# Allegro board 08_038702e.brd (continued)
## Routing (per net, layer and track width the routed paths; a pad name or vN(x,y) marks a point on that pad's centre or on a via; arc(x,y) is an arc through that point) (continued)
JX_VCCO_13_SEQ: length 4.7
  TOP w0.14: R71.1 R72.2 13.77,38.97 13.51,38.72 11.61,38.72 11.08,39.24 U7.8
JX_VCCO_33_34: length 14.4
  TOP w0.254: R73.1 v1(15.17,39.73)
  TOP w0.305: v1(15.17,39.73) v1(15.67,39.73) 15.86,39.54 Q10.1 ; Q10.1 Q10.2 Q10.5 ; Q10.1 Q10.6
  L14_SIG w0.508: v1(15.67,39.73) v1(15.17,39.73)
  BOTTOM w0.508: JX2.78 61.52,6.56 61.52,6.84 61.9,7.22 61.9,9.04 62.33,9.47 JX2.79 ; JX2.78 61.53,4.05 61.39,3.92 v1(61.39,3.79) ; JX2.78 61.53,6.72 61.77,6.97 62.28,6.97 v1(62.33,6.92) JX2.80
JX_VCCO_33_34_SEQ: length 4
  TOP w0.14: U7.9 11.58,39.38 11.86,39.1 12.63,39.1 12.82,39.29 13.64,39.29 R73.2 R74.1
JX_VIN: length 29.7
  TOP w0.305: Q13.PAD1 16.44,43.36 Q13.5 ; Q13.PAD1 15.79,43.36 Q13.6 ; Q13.PAD1 16.44,42.71 Q13.2 ; Q13.PAD1 15.79,42.71 Q13.1
  TOP w0.406: Q13.1 15.79,41.75 15.17,41.13 v1(15.04,41.13) 14.71,41.13 v1(14.66,41.18)
  L7_SIG w0.406: v1(54.33,4.6) 54.33,6.03 53.9,6.46 53.9,8.92 54.28,9.3 v1(54.28,9.63) 54.28,9.97 v1(54.33,10.01)
  L17_SIG w0.406: v1(53.53,4.56) 54.29,4.56 v1(54.33,4.6)
  BOTTOM w0.203: D1.1 66.04,46.64 65.84,46.84 v1(65.33,46.84)
  BOTTOM w0.254: JX2.59 v1(54.33,10.01)
  BOTTOM w0.508: v1(35.36,4.17) 35.36,5.23 35.13,5.47 JX2.12 ; JX1.59 54.33,56.32 v5(53.77,56.88) 53.53,56.63 JX1.57 ; JX2.60 v1(54.33,4.6) ; v1(53.53,4.56) JX2.58 ; v1(54.33,10.01) 54.24,10.11 54.24,10.23 53.53,10.94 JX2.57 ; JX1.58 53.53,49.76 53.9,49.38 v5(54.03,49.38) 54.15,49.51 54.15,49.64 54.33,49.81 JX1.60
  vias: v1(15.24,43.16) v1(15.32,43.67) v1(16.18,41.76) v3(58.73,21.7) v3(59.23,21.7) v5(53.52,49.38) v5(54.28,56.88)
MGTAVCC: length 10.5
  TOP w0.203: U1.AD6 v1(23.22,38.59) ; U1.AE8 v1(22.22,36.59) ; U1.R4 v1(32.22,40.59) ; U1.AA4 v1(26.22,40.59) ; U1.AC8 v1(24.22,36.59) ; U1.AA8 v1(26.22,36.59) ; U1.Y6 v1(27.22,38.59) ; U1.T6 v1(31.22,38.59) ; U1.U4 v1(30.22,40.59) ; U1.AB6 v1(25.22,38.59)
  TOP w0.305: Q8.4 8.56,37.19 8.94,37.57 v1(9.5,37.57) v1(9.96,37.57)
  BOTTOM w0.305: C222.1 v1(18.21,36.05)
  BOTTOM w0.508: C64.1 26.34,40.46 v1(26.22,40.59) ; C220.1 v1(18.21,38.84)
MGTAVCC_EN: length 16.3
  TOP w0.14: v1(9.58,35.41) 8.82,35.41 8.56,35.67 Q8.3 ; v1(10.21,46.59) 10.08,46.46 U7.25
  L3_SIG w0.095: v1(10.21,46.59) 11.74,45.07 11.74,37.7 10.81,36.77 9.41,36.77 8.94,36.3 8.94,35.67 9.2,35.41 v1(9.58,35.41)
MGTAVTT: length 11.4
  TOP w0.203: U1.T2 v1(31.22,42.59) ; U1.AE4 v1(22.22,40.59) ; U1.AB2 v1(25.22,42.59) ; U1.AD2 v1(23.22,42.59) ; U1.AB7 v1(25.22,37.59) ; U1.Y2 v1(27.22,42.59) ; U1.AF6 v1(21.22,38.59) ; U1.AC4 v1(24.22,40.59) ; U1.V2 v1(29.22,42.59) ; U1.W4 v1(28.22,40.59) ; U1.AF2 v1(21.22,42.59)
  TOP w0.305: Q7.4 10.34,35.16 v1(10.59,34.91) v1(10.97,34.53)
  BOTTOM w0.508: v1(24.22,40.59) 24.31,40.49 C234.1 ; 19.61,37.57 v1(19.61,38.34) ; C223.1 v1(20.37,44.94) ; C221.1 v1(20.37,42.53)
MGTAVTT_EN: length 14.7
  TOP w0.14: Q7.3 10.34,37.15 v1(10.38,37.19) ; U7.26 9.58,46.46 9.1,46.94 9.1,47.13 v1(9.7,47.73)
  L3_SIG w0.095: v1(9.7,47.73) 9.7,47.45 9.36,47.11 9.36,46.83 9.7,46.49 9.7,44.81 11.1,43.42 11.1,42.22 11.38,41.94 11.38,41.6 11.12,41.34 11.12,38.36 10.38,37.62 v1(10.38,37.19)
MGTREFCLK0_112_JX1_N: length 66.9
  L14_SIG w0.089: v1(66.22,53.58) 66.22,54.59 66.47,54.85 71.05,54.85 71.3,55.1 71.3,56.12 71.05,56.37 63.83,56.37 63.43,55.97 63.43,54.57 63.32,54.46 62.51,54.46 62.41,54.57 62.41,55.97 62.01,56.37 60.65,56.37 60.25,55.97 60.25,55.08 60.14,54.97 59.21,54.97 59.11,55.08 59.11,55.97 58.7,56.37 57.6,56.37 56.08,54.85 47.73,54.85 46.49,53.6 46.05,53.6 45.85,53.4 45.44,53.4 45.18,53.14 44.9,53.14 44.89,53.15 43.31,53.15 41.96,51.8 39.8,51.8 39.31,51.3 39.31,48.85 39.2,48.75 37.16,48.75 36.76,48.35 36.76,46.44 36.27,45.96 34.6,45.96 33.82,45.18 33.82,44.08 34.22,43.69 34.22,39.58 33.86,39.22 33.58,39.22 v1(33.22,39.59)
  BOTTOM w0.089: v1(66.22,53.58) 66.05,53.74 66.05,54.34 66.33,54.61 JX1.89 ; C45.1 33.01,39.38 v1(33.22,39.59)
MGTREFCLK0_112_JX1_P: length 66.8
  L14_SIG w0.089: v1(33.22,38.59) 33.58,38.95 33.58,38.97 33.96,38.97 34.47,39.48 34.47,43.8 34.08,44.19 34.08,45.08 34.7,45.7 36.37,45.7 37.01,46.34 37.01,48.24 37.26,48.5 39.31,48.5 39.56,48.75 39.56,51.19 39.91,51.54 42.07,51.54 43.42,52.89 44.79,52.89 44.79,52.89 45.28,52.89 45.55,53.15 45.96,53.15 46.16,53.35 46.6,53.35 47.84,54.59 56.19,54.59 57.71,56.12 58.6,56.12 58.85,55.86 58.85,54.97 59.11,54.72 60.25,54.72 60.5,54.97 60.5,55.86 60.76,56.12 61.9,56.12 62.16,55.86 62.16,54.46 62.41,54.21 63.43,54.21 63.68,54.46 63.68,55.86 63.93,56.12 70.94,56.12 71.05,56.01 71.05,55.2 70.94,55.1 66.53,55.1 66.53,55.1 66.37,55.1 65.97,54.7 65.97,54.59 65.84,54.46 65.84,54.21 65.97,54.08 65.97,53.96 v1(65.58,53.58)
  BOTTOM w0.089: C47.1 33.01,38.38 v1(33.22,38.59) ; v1(65.58,53.58) 65.84,53.83 65.84,54.34 65.53,54.65 JX1.87
MGTREFCLK1_112_JX3_N: length 68.5
  L3_SIG w0.089: v1(13.77,12.17) 13.58,11.98 13.01,11.98 12.77,11.75 12.77,10.91 14.53,9.15 14.53,4.58 14.93,4.17 15.93,4.17 16.18,3.92 16.18,3.56 16.58,3.16 17.83,3.16 18.09,3.41 18.09,10.9 18.3,11.11 18.3,12.06 18.49,12.26 19.95,12.26 20.37,12.68 22.26,12.68 22.66,13.08 22.66,16.62 22.15,17.13 20.75,17.13 20.5,17.38 20.5,35.56 20.73,35.8 20.95,35.8 21.08,35.92 29.46,35.92 29.88,36.34 29.88,38.84 29.49,39.22 28.69,39.22 28.68,39.22 28.59,39.22 v1(28.22,39.59)
  BOTTOM w0.089: v1(28.22,39.59) 28.58,39.22 29.39,39.22 29.61,39 C48.1 ; v1(13.77,12.17) 13.58,11.98 13.45,11.98 13.26,12.17 JX3.4
MGTREFCLK1_112_JX3_P: length 68.4
  L3_SIG w0.089: v1(13.77,11.54) 13.58,11.73 13.11,11.73 13.02,11.64 13.02,11.01 14.78,9.25 14.78,4.68 15.04,4.43 16.03,4.43 16.44,4.02 16.44,3.66 16.69,3.41 17.73,3.41 17.83,3.52 17.83,11.01 18.04,11.22 18.04,12.16 18.39,12.51 19.84,12.51 20.27,12.94 22.15,12.94 22.4,13.19 22.4,16.51 22.04,16.87 20.65,16.87 20.25,17.28 20.25,35.67 20.63,36.05 20.84,36.05 20.97,36.18 29.36,36.18 29.63,36.45 29.63,38.73 29.39,38.97 28.79,38.97 28.78,38.96 28.48,38.96 28.3,39.15 27.92,39.15 27.74,38.97 27.74,38.42 27.83,38.34 27.96,38.34 v1(28.22,38.59)
  BOTTOM w0.089: v1(28.22,38.59) 28.69,38.11 C46.1 ; v1(13.77,11.54) 13.64,11.67 13.51,11.67 13.22,11.37 JX3.2
MGTXRX0_112_JX1_N: length 66.8
  TOP w0.089: U1.AB3 v1(25.22,41.59)
  L6_SIG w0.089: v1(25.22,41.59) 24.88,41.25 22.04,41.25 21.97,41.18 21.63,40.83 21.63,40.34 21.64,40.33 21.64,39.33 21.54,39.22 20.1,39.22 19.99,39.33 19.99,45.6 20.1,45.7 35.72,45.7 36.99,46.97 44.38,46.97 45.39,47.99 52.48,47.99 52.99,48.5 54.81,48.5 55.06,48.24 55.06,47.35 55.32,47.1 56.87,47.1 57.15,46.83 57.64,46.83 57.68,46.86 58.47,46.86 58.71,47.1 59.38,47.1 59.61,46.86 61.16,46.86 61.38,46.89 61.77,46.89 61.89,47.02 62.53,47.02 62.61,47.1 63.22,47.1 63.31,47.02 64.61,47.02 65.19,47.59 65.44,47.59 65.84,47.99 65.84,48.88 65.97,49 66.17,49 66.35,49.18 66.35,49.33 v1(66.03,49.65)
  BOTTOM w0.089: JX1.90 66.33,50.25 65.97,49.89 65.97,49.71 v1(66.03,49.65)
MGTXRX0_112_JX1_P: length 66.8
  TOP w0.089: U1.AB4 v1(25.22,40.59)
  L6_SIG w0.089: v1(65.52,49.64) 65.58,49.57 65.58,48.09 65.34,47.85 65.09,47.85 64.51,47.27 63.41,47.27 63.33,47.35 62.5,47.35 62.42,47.27 61.79,47.27 61.66,47.14 61.19,47.14 61.16,47.12 61.15,47.12 59.72,47.12 59.48,47.35 58.6,47.35 58.37,47.12 57.57,47.12 57.53,47.08 57.25,47.08 56.98,47.35 55.42,47.35 55.32,47.46 55.32,48.35 54.92,48.75 54.71,48.75 52.88,48.75 52.38,48.24 45.26,48.24 44.25,47.23 36.88,47.23 35.61,45.96 19.99,45.96 19.74,45.7 19.74,39.22 19.99,38.97 21.64,38.97 21.9,39.22 21.9,40.43 21.88,40.45 21.88,40.73 22.08,40.92 22.08,40.92 22.15,41 24.81,41 v1(25.22,40.59)
  BOTTOM w0.089: v1(65.52,49.64) 65.75,49.87 65.75,49.89 65.53,50.11 JX1.88
MGTXRX1_112_JX1_N: length 67.9
  TOP w0.089: U1.Y3 v1(27.22,41.59)
  L4_SIG w0.089: v1(67.74,53.58) 67.74,53.91 67.62,54.03 67.62,54.57 66.83,55.35 36.08,55.35 30.54,49.81 30.54,49.75 28.65,47.86 27.76,47.86 27.44,47.54 27.44,47.09 27.36,47 27.36,46.1 27.76,45.7 33.22,45.7 33.83,45.09 33.83,40.6 33.47,40.24 29.09,40.24 28.81,40.52 28.81,40.83 28.46,41.18 27.82,41.18 27.78,41.22 27.59,41.22 v1(27.22,41.59)
  BOTTOM w0.089: JX1.93 67.93,54.69 67.58,54.34 67.58,53.74 v1(67.74,53.58)
MGTXRX1_112_JX1_P: length 68
  TOP w0.089: U1.Y4 v1(27.22,40.59)
  L4_SIG w0.089: v1(27.22,40.59) 27.1,40.7 27.1,41 27.21,41.11 27.34,41.11 27.48,40.96 27.68,40.96 27.71,40.92 28.35,40.92 28.55,40.73 28.55,40.42 28.98,39.99 33.58,39.99 34.09,40.49 34.09,45.19 33.33,45.96 27.87,45.96 27.61,46.21 27.61,46.9 27.69,46.98 27.69,47.44 27.87,47.61 28.75,47.61 30.79,49.64 30.79,49.7 36.19,55.1 66.73,55.1 67.36,54.46 67.36,54.03 67.24,53.91 v1(67.24,53.58)
  BOTTOM w0.089: v1(67.24,53.58) 67.36,53.7 67.36,54.34 67.13,54.57 JX1.91
MGTXRX2_112_JX1_N: length 66.8
  TOP w0.089: U1.V3 v1(29.22,41.59)
  L6_SIG w0.089: v1(67.74,49.69) 67.92,49.51 68.07,49.51 68.2,49.38 68.2,49.21 68,49 67.87,49 67.74,48.88 67.74,46.1 66.95,45.31 64.86,45.31 63.94,46.23 52.29,46.23 52.24,46.29 51.96,46.29 51.9,46.23 49.46,46.23 49.18,45.96 38.38,45.96 36.35,43.92 34.6,43.92 34.34,43.67 34.34,42.25 34.09,42 32.82,42 32.56,42.25 32.56,43.67 32.55,43.68 32.55,43.73 32.35,43.92 32.31,43.92 32.31,43.92 22,43.92 21.9,43.82 21.9,42.28 22,42.18 26.46,42.18 26.88,41.76 26.88,41.45 27.08,41.25 28.88,41.25 v1(29.22,41.59)
  BOTTOM w0.089: JX1.94 67.93,50.33 67.62,50.02 67.62,49.81 v1(67.74,49.69)
MGTXRX2_112_JX1_P: length 66.8
  TOP w0.089: U1.V4 v1(29.22,40.59)
  L6_SIG w0.089: v1(67.24,49.69) 67.49,49.43 67.49,46.21 66.84,45.56 64.97,45.56 64.04,46.49 52.4,46.49 52.34,46.55 51.85,46.55 51.8,46.49 49.35,46.49 49.07,46.21 38.28,46.21 36.25,44.18 34.49,44.18 34.09,43.78 34.09,42.36 33.98,42.25 32.92,42.25 32.82,42.36 32.82,43.78 32.81,43.79 32.81,43.83 32.46,44.18 32.42,44.18 21.9,44.18 21.64,43.92 21.64,42.18 21.9,41.92 26.35,41.92 26.63,41.65 26.63,41.34 26.97,41 28.81,41 v1(29.22,40.59)
  BOTTOM w0.089: JX1.92 67.13,50.29 67.4,50.02 67.4,49.85 v1(67.24,49.69)
MGTXRX3_112_JX1_N: length 66.8
  TOP w0.089: U1.T3 v1(31.22,41.59)
  L4_SIG w0.089: v1(70.16,53.58) 70.16,53.91 69.97,54.1 69.97,54.53 68.12,56.37 35,56.37 28.13,49.5 26.97,49.5 25.45,47.99 25.45,45.47 26.74,44.18 32.2,44.18 32.55,43.83 32.55,41.45 32.35,41.25 31.55,41.25 v1(31.22,41.59)
  BOTTOM w0.089: JX1.99 70.33,54.67 69.99,54.34 69.99,53.74 v1(70.16,53.58)
MGTXRX3_112_JX1_P: length 66.7
  TOP w0.089: U1.T4 v1(31.22,40.59)
  L4_SIG w0.089: v1(31.22,40.59) 31.17,40.64 31.17,41 31.24,41.07 31.37,41.07 31.45,41 32.46,41 32.81,41.34 32.81,43.94 32.31,44.43 26.85,44.43 25.71,45.57 25.71,47.88 27.07,49.25 28.24,49.25 35.1,56.12 68.02,56.12 69.71,54.42 69.71,54.1 69.52,53.91 v1(69.52,53.58)
  BOTTOM w0.089: v1(69.52,53.58) 69.78,53.83 69.78,54.34 69.53,54.59 JX1.97
MGTXTX0_112_JX3_N: length 67.3
  TOP w0.089: U1.AA1 v1(26.22,43.59)
  L3_SIG w0.089: v1(16.82,16.11) 17.08,16.31 17.16,16.31 17.42,16.56 17.42,17.89 17.16,18.14 17.07,18.14 16.82,18.4 16.82,19.41 17.07,19.67 18.06,19.67 18.47,19.26 18.47,14.23 18.06,13.82 13.87,13.82 13.77,13.72 13.77,13.29 13.87,13.19 18.91,13.19 19.02,13.29 19.02,14.44 19.42,14.84 21.54,14.84 21.64,14.95 21.64,15.37 21.54,15.48 19.42,15.48 19.02,15.88 19.02,31.1 18.59,31.52 18.59,33.64 19.02,34.06 19.02,36.35 19.86,37.19 20.88,37.19 21.9,38.21 21.9,39.46 22.91,40.47 22.91,41.64 24.45,43.18 25.46,43.18 25.48,43.16 25.79,43.16 v1(26.22,43.59)
  BOTTOM w0.089: v1(16.82,16.11) 16.82,15.78 16.38,15.35 15.46,15.35 14.4,14.29 13.64,14.29 13.36,14.57 JX3.10
MGTXTX0_112_JX3_P: length 67.3
  TOP w0.089: U1.AA2 v1(26.22,42.59)
  L3_SIG w0.089: v1(17.2,15.6) 17.41,15.76 17.41,16.2 17.67,16.46 17.67,17.99 17.27,18.4 17.18,18.4 17.07,18.5 17.07,19.31 17.18,19.41 17.96,19.41 18.21,19.16 18.21,14.33 17.96,14.08 13.77,14.08 13.51,13.82 13.51,13.19 13.77,12.94 19.02,12.94 19.27,13.19 19.27,14.33 19.53,14.59 21.64,14.59 21.9,14.84 21.9,15.48 21.64,15.73 19.53,15.73 19.27,15.98 19.27,31.2 18.85,31.63 18.85,33.53 19.27,33.96 19.27,36.24 19.97,36.94 20.99,36.94 22.15,38.1 22.15,39.35 23.17,40.37 23.17,41.53 24.56,42.92 25.35,42.92 25.37,42.91 25.9,42.91 v1(26.22,42.59)
  BOTTOM w0.089: v1(17.2,15.6) 16.94,15.6 16.47,15.13 15.55,15.13 14.49,14.08 13.64,14.08 13.33,13.77 JX3.8
MGTXTX1_112_JX3_N: length 67.3
  TOP w0.089: U1.W1 v1(28.22,43.59)
  L18_SIG w0.089: v1(28.22,43.59) 27.84,43.22 22.59,43.22 20.12,40.75 20.12,40.16 18.98,39.01 18.98,35.54 17.45,34.02 12.98,34.02 12.75,34.25 12.75,34.56 12.67,34.64 12.67,34.92 12.75,35 12.75,35.31 13.13,35.69 13.13,38.52 12.69,38.97 12.06,38.97 11.61,38.52 11.61,33.13 12.24,32.49 12.37,32.49 12.75,32.11 12.75,30.21 13.13,29.83 15.42,29.83 15.67,30.08 15.67,32.24 15.93,32.49 16.38,32.49 16.56,32.31 16.56,30.92 17.14,30.33 17.58,30.33 18.09,29.83 18.09,27.79 17.32,27.03 16.69,27.03 15.67,26.02 14.78,26.02 13.01,24.24 13.01,19.54 11.86,18.4 11.13,18.4 10.2,17.47 9.86,17.13 v1(9.7,17.13)
  BOTTOM w0.089: v1(9.7,17.13) 9.7,16.87 9.45,16.62 9.2,16.62 8.84,16.97 JX3.15
MGTXTX1_112_JX3_P: length 67.3
  TOP w0.089: U1.W2 v1(28.22,42.59)
  L18_SIG w0.089: v1(10.21,16.75) 10.21,17.12 11.23,18.14 11.97,18.14 13.26,19.43 13.26,24.13 14.89,25.76 15.78,25.76 16.79,26.78 17.43,26.78 18.34,27.69 18.34,29.93 17.68,30.59 17.25,30.59 16.82,31.02 16.82,32.41 16.48,32.75 15.82,32.75 15.42,32.34 15.42,30.19 15.31,30.08 13.24,30.08 13.01,30.31 13.01,32.22 12.48,32.75 12.35,32.75 11.86,33.23 11.86,38.42 12.16,38.72 12.58,38.72 12.88,38.42 12.88,35.8 12.5,35.41 12.5,35.11 12.42,35.02 12.42,34.53 12.5,34.45 12.5,34.14 12.88,33.76 17.56,33.76 19.23,35.44 19.23,38.91 20.37,40.05 20.37,40.64 22.69,42.96 27.84,42.96 v1(28.22,42.59)
  BOTTOM w0.089: JX3.13 8.97,16.17 9.2,16.4 9.54,16.4 9.88,16.75 v1(10.21,16.75)
MGTXTX2_112_JX3_N: length 67.3
  TOP w0.089: U1.U1 v1(30.22,43.59)
  L3_SIG w0.089: v1(30.22,43.59) 29.84,43.22 29.75,43.22 29.72,43.25 29.14,43.25 29.08,43.25 28.88,43.45 28.88,44.05 28.43,44.51 21.08,44.51 19.61,43.03 19.61,40.37 18.68,39.44 18.68,37.51 17.58,36.41 17.58,35.92 17.32,35.67 11.61,35.67 11.36,35.41 11.36,33.91 11.76,33.51 17.22,33.51 17.32,33.4 17.32,31.2 17.22,31.1 15.67,31.1 15.42,31.35 14.4,31.35 14.15,31.1 11.61,31.1 11.36,30.84 11.36,29.32 11.61,29.06 15.67,29.06 15.93,29.32 17.07,29.32 17.58,28.81 17.58,21.55 14.78,18.76 14.78,16.94 14.59,16.75 14.48,16.75 14.35,16.87 v1(14.02,16.87)
  BOTTOM w0.089: JX3.16 13.38,16.97 13.64,16.71 13.86,16.71 v1(14.02,16.87)
MGTXTX2_112_JX3_P: length 67.3
  TOP w0.089: U1.U2 v1(30.22,42.59)
  L3_SIG w0.089: v1(30.22,42.59) 29.84,42.96 29.65,42.96 29.61,43 29.03,43 28.97,43 28.63,43.34 28.63,43.95 28.32,44.25 21.19,44.25 19.86,42.93 19.86,40.26 18.94,39.33 18.94,37.41 17.83,36.3 17.83,35.82 17.43,35.41 11.71,35.41 11.61,35.31 11.61,34.02 11.86,33.76 17.32,33.76 17.58,33.51 17.58,31.1 17.32,30.84 15.57,30.84 15.31,31.1 14.51,31.1 14.25,30.84 11.71,30.84 11.61,30.74 11.61,29.42 11.71,29.32 15.57,29.32 15.82,29.57 17.18,29.57 17.83,28.92 17.83,21.44 15.04,18.65 15.04,16.83 14.7,16.49 14.48,16.49 14.35,16.36 v1(14.02,16.36)
  BOTTOM w0.089: JX3.14 13.32,16.17 13.64,16.49 13.9,16.49 v1(14.02,16.36)
MGTXTX3_112_JX3_N: length 67.7
  TOP w0.089: U1.R1 v1(32.22,43.59)
  L18_SIG w0.089: v1(32.22,43.59) 31.86,43.24 30.09,43.24 29.88,43.45 29.88,43.76 29.33,44.3 20.5,44.3 19.78,43.59 19.78,41.55 19.23,41 19.23,40.47 18.19,39.43 17.97,39.43 17.63,39.1 16.05,39.1 15.91,39.24 14.28,39.24 13.9,39.62 13.9,40.02 13.69,40.23 13.69,41.78 13.9,41.99 13.9,42.53 13.51,42.91 11.61,42.91 11.38,42.68 11.38,41.61 11.23,41.45 11.23,40.37 10.85,39.99 8.82,39.99 8.43,39.61 8.43,33.76 11.74,30.46 11.74,28.81 12.12,28.43 14.28,28.43 14.78,28.94 15.9,28.94 16.09,28.75 16.09,28.48 16.35,28.23 16.35,27.95 16.16,27.75 15.72,27.75 15.01,27.03 14.53,27.03 11.74,24.24 11.74,19.79 11.31,19.37 11.31,19.29 11.05,19.03 10.29,19.03 10.16,19.16 v1(9.83,19.16)
  BOTTOM w0.089: v1(9.83,19.16) 9.7,19.03 9.2,19.03 8.86,19.37 JX3.21
MGTXTX3_112_JX3_P: length 67.7
  TOP w0.089: U1.R2 v1(32.22,42.59)
  L18_SIG w0.089: v1(32.22,42.59) 31.82,42.98 29.99,42.98 29.63,43.34 29.63,43.65 29.23,44.05 20.6,44.05 20.04,43.48 20.04,41.45 19.48,40.9 19.48,40.37 18.3,39.18 18.07,39.18 17.74,38.84 15.95,38.84 15.8,38.99 14.17,38.99 13.64,39.52 13.64,39.91 13.43,40.12 13.43,41.88 13.64,42.09 13.64,42.42 13.41,42.65 11.71,42.65 11.64,42.57 11.64,41.5 11.48,41.35 11.48,40.26 10.95,39.73 8.92,39.73 8.69,39.5 8.69,33.87 11.99,30.57 11.99,28.92 12.22,28.68 14.17,28.68 14.68,29.19 16.01,29.19 16.35,28.85 16.35,28.59 16.61,28.33 16.61,27.84 16.26,27.5 15.83,27.5 15.11,26.78 14.64,26.78 11.99,24.13 11.99,19.69 11.56,19.26 11.56,19.19 11.15,18.78 10.29,18.78 10.16,18.65 v1(9.83,18.65)
  BOTTOM w0.089: JX3.19 8.95,18.57 9.2,18.82 9.67,18.82 v1(9.83,18.65)
Net_65: length 0.6
  TOP w0.14: v6(70,30.49) 69.6,30.09
PG_1P8V: length 16.7
  TOP w0.305: v1(70.41,5.06) 69.86,5.61 U19.4 ; v1(67.24,4.43) 66.73,4.93 66.73,5.35 66.68,5.4 66.66,5.42 66.24,5.84 64.17,5.84 63.81,6.2 R81.1 63.3,6.84 62.79,7.35 62.54,7.35 62.26,7.62 U4.1
  TOP w0.381: U20.4 79.51,6.37 v1(79.81,6.08)
  L3_SIG w0.406: v1(34.47,4.93) 34.47,3.86 35.17,3.16 36.37,3.16 37.26,2.27 v1(37.64,2.27)
  BOTTOM w0.508: JX2.10 34.33,5.08 v1(34.47,4.93)
PG_MODULE: length 90.9
  TOP w0.14: Q14.1 v1(30.51,50.68) ; R43.2 30.66,11.79 v1(30.41,12.05) ; v1(14.49,46.59) 14.49,46.54 14.22,46.27 14.22,46.27 14.09,46.15 13.74,46.15 13.42,46.46 12.37,46.46 12.08,46.17 U7.21
  L3_SIG w0.095: v1(30.41,12.05) 30.91,12.05 31.93,13.06 v3(34.22,13.06)
  L14_SIG w0.095: v1(30.51,50.68) 30.48,50.65 29.26,50.65 27.23,48.62 20.25,48.62 19.36,47.73 16.31,47.73 15.17,46.59 v1(14.49,46.59)
  L18_SIG w0.095: v1(30.51,50.68) 30.53,50.65 30.53,47.86 31.42,46.97 32.35,46.97 32.61,46.72 32.61,44.8 32.8,44.6 33.41,44.6 34.72,43.29 34.72,36.43 35.23,35.93 35.36,35.93 35.56,35.73 35.56,34.04 35.78,33.82 35.78,33.15 36,32.93 36.36,32.93 36.54,32.75 36.64,32.75 36.88,32.51 36.88,32.45 37.07,32.25 37.14,32.25 37.27,32.11 37.37,32.11 37.75,31.73 37.75,31.35 39.18,29.93 39.36,29.93 39.56,29.73 39.56,29.55 39.88,29.23 39.88,28.63 39.55,28.31 39.45,28.31 38.88,27.73 38.88,27.11 38.7,26.93 38.07,26.93 37.88,26.73 37.55,26.73 37.36,26.93 35.07,26.93 34.93,26.78 33.51,26.78 33.36,26.93 33.07,26.93 32.88,26.73 32.88,26.11 32.7,25.93 32.06,25.93 31.16,25.03 30.17,25.03 29.78,24.64 29.78,24.36 29.45,24.03 29.17,24.03 28.88,23.73 28.88,23.45 28.39,22.97 27.12,22.97 26.82,22.67 26.82,20.27 26.93,20.15 27.45,20.15 27.83,19.76 27.83,18.44 28.12,18.15 28.45,18.15 28.78,17.82 28.78,17.49 29.44,16.83 29.66,16.83 30.63,15.86 32.95,15.86 34.6,14.21 34.6,13.44 v3(34.22,13.06)
  L19_GND w0.203: v3(34.22,13.06) 34.34,13.06 v4(35.13,12.28)
  BOTTOM w0.14: v4(35.13,12.28) JX2.11
PHY1_1V8: length 12.8
  TOP w0.406: E14.2 v1(30.91,2.01)
  TOP w0.508: C78.1 16.35,17.67 v1(16.18,17.51)
  BOTTOM w0.305: U10.10 v1(20.39,2.39) 20.12,2.39 19.89,2.62 U10.11 ; v1(27.1,8.74) v1(27.1,8.24) 27.1,7.86 26.59,7.34 U10.49 25.59,7.35 24.94,7.35 24.69,7.09 24.69,6.08 24.92,5.84 U10.52
  BOTTOM w0.406: v1(30.91,2.01) 31.17,2.27 v1(31.17,2.78) ; v1(29.77,4.43) 29.14,3.79 R11.1
  BOTTOM w0.508: v1(15.42,3.79) 15.55,3.79 15.8,4.05 C74.1 ; C206.1 v1(15.8,6.46)
PHY1_AVDD_1V8: length 117.5
  TOP w0.305: C201.1 C218.1 22.28,12.43 v1(22.89,11.81)
  TOP w0.508: C211.1 v1(19.23,11.79) 18.47,11.03 C203.1
  L3_SIG w0.406: v1(72.44,11.28) v1(73.2,11.28)
  L3_SIG w0.508: v1(22.89,11.81) 23.7,11 24.22,11 24.32,10.9 27.99,10.9 28.5,10.4 35.1,10.4 36.12,9.38 36.12,4.81 37.52,3.41 43.49,3.41 43.87,3.03 50.98,3.03 52.25,1.76 63.04,1.76 65.08,3.79 65.08,5.82 67.36,8.11 67.36,10.14 68,10.78 69.78,10.78 70.66,11.67 72.06,11.67 v1(72.44,11.28)
  L19_GND w0.305: v4(18.7,5.84) v3(19.21,5.84)
  L19_GND w0.406: v4(23.89,4.17) 23.93,4.17 24.44,4.68 v3(24.44,5.06)
  BOTTOM w0.254: v1(16.18,9.89) 16.4,9.67 16.61,9.67 16.94,9.34 U10.26 ; v4(23.89,4.17) U10.3
  BOTTOM w0.305: U10.39 23.39,10.62 22.91,10.14 22.69,10.14 v1(22.53,9.99) ; U10.38 v1(22.89,11.81) ; U10.35 21.39,11.66 v1(21.26,11.79) ; v1(74.47,42.15) 74.74,42.15 75.13,42.53 U24.5 ; U10.19 v4(18.7,5.84)
  BOTTOM w0.406: C210.1 22.15,13.57 21.26,12.68 v1(21.26,11.79) ; v1(72.44,11.28) v1(73.2,11.28) 74.22,12.3 74.22,16.49 77.14,19.41 77.14,37.07 75.62,38.59 74.6,38.59 73.59,39.61 73.59,41.26 v1(74.47,42.15)
  BOTTOM w0.508: v1(14.02,8.74) 14.44,9.16 C219.1
PHY1_AVDD_3V3: length 8.7
  TOP w0.406: C208.1 15.8,9.25 v1(16.44,9.25) ; C49.1 v1(17.71,11.92)
  TOP w0.508: C217.1 v1(24.82,12.55) ; E15.2 v1(15.55,18.02)
  L19_GND w0.305: v3(19.23,6.59) 18.99,6.34 v4(18.46,6.34)
  BOTTOM w0.203: 16.96,6.34 U10.20
  BOTTOM w0.254: v1(16.44,9.25) 16.78,8.91 16.99,8.91 17.06,8.84 U10.25
  BOTTOM w0.305: U10.20 v4(18.46,6.34)
  BOTTOM w0.508: C214.1 16.93,6.34 16.96,6.34
PHY1_DVDD_1V0: length 22.4
  TOP w0.406: C63.1 v1(27.87,12.55)
  TOP w0.457: v1(24.89,11.74) 24.85,11.7 v1(23.89,11.7)
  TOP w0.508: v1(27.87,12.55) 28.08,12.34 C58.1 ; v1(23.89,11.7) 23.8,11.79 C73.1 ; C63.1 v1(26.21,12.55)
  L6_SIG w0.508: v1(22.15,1.51) 22.15,2.01 23.29,3.16 23.8,3.16 24.94,4.3 24.94,4.8 24.98,4.84 24.98,5.29 24.94,5.33 24.94,5.95 25.71,6.71 25.71,9.63 24.89,10.45 v1(24.89,11.74)
  BOTTOM w0.254: U10.6 22.39,2.8 22.42,2.78
  BOTTOM w0.305: v1(22.15,1.51) 22.15,2.51 22.42,2.78 ; U10.40 v1(23.89,11.7) ; U10.42 v1(24.89,11.74)
  BOTTOM w0.406: v1(22.15,1.51) 22.28,1.38 C75.1
  BOTTOM w0.508: v1(24.89,11.74) 25.71,12.55 v1(26.21,12.55)
PHY1_LED_0: length 78.2
  TOP w0.508: Q2.1 12.9,56.5 v1(13.64,56.5) R14.1
  L18_SIG w0.254: v1(16.31,1.76) 16.05,2.01 8.82,2.01 7.42,3.41 7.42,6.33 6.91,6.84 4.75,6.84 1.58,10.01 1.58,21.83 2.97,23.22 2.97,48.75 10.72,56.5 v1(13.64,56.5)
  BOTTOM w0.254: U10.14 18.39,2.83 18.21,2.65 17.07,2.65 16.31,1.89 v1(16.31,1.76)
PHY1_LED_1: length 24.9
  TOP w0.508: Q1.1 33.38,10.07 32.95,9.63 v1(32.82,9.63) 32.69,9.63 32.31,10.01 R13.1
  L6_SIG w0.381: 32.18,9.25 32.56,9.63 v1(32.82,9.63)
  L6_SIG w0.508: 32.18,9.25 32.18,8.62 32.44,8.36 32.44,7.6 31.04,6.2 31.04,4.17 29.01,2.14 29.01,1.38 28.16,0.53 20.63,0.53 20.37,0.78 v1(20.37,1.76)
  BOTTOM w0.254: U10.13 18.89,2.6 19.74,1.76 v1(20.37,1.76)
PHY1_VDD_3V3: length 103.3
  TOP w0.305: C225.1 v1(28.5,11.41) ; C50.1 v1(25.83,11.54)
  TOP w0.406: 33.71,4.81 v1(32.69,4.81)
  TOP w0.508: R16.1 v1(8.18,58.27) ; E16.2 15.67,12.74 v1(15.67,12.05) ; v1(21.52,10.01) 21.26,10.27 C226.1
  L6_SIG w0.406: v3(16.75,4.36) 17.77,4.36 18.47,5.06 18.47,8.74 19.23,9.51 21.01,9.51 v1(21.52,10.01)
  L7_SIG w0.508: v1(32.69,4.81) 31.55,3.66 30.15,3.66 29.14,2.65 29.14,1.51 28.21,0.58 19.39,0.58 18.09,1.89 18.09,3.03 v3(16.75,4.36) 16.31,4.81 10.59,4.81 9.32,6.08 9.32,6.71 7.42,8.62 5.51,8.62 3.86,10.27 3.86,14.33 3.01,15.18 3.01,18.1 2.21,18.9 2.21,22.97 2.72,23.48 2.72,33.76 3.23,34.27 3.23,49.51 8.18,54.46 v1(8.18,58.27)
  BOTTOM w0.305: v1(21.52,10.01) 21.89,10.39 U10.36
PS-SRST#: length 70.3
  TOP w0.14: 43.74,5.82 43.87,5.95 43.87,7.58 Q5.2 43.87,7.68 v1(43.87,8.74) ; U1.A22 v1(47.22,21.59)
  L15_SIG w0.095: v1(47.22,21.59) 47.23,21.57 53.01,21.57 54.66,19.92 66.35,19.92 70.41,23.98 70.41,26.14 71.3,27.03 71.3,33.38 70.03,34.65 70.03,38.08 68.89,39.22 v1(68.89,45.19)
  L18_SIG w0.095: v1(47.22,21.59) 46.7,21.59 46.13,21.03 44.12,21.03 43.56,20.46 43.56,20.45 42.78,19.67 42.78,17.31 42.09,16.62 42.09,10.52 v1(43.87,8.74)
  BOTTOM w0.14: R19.1 v1(68.89,45.19)
PS_1.35V_EN: length 93.7
  TOP w0.14: U7.22 11.58,46.44 12.37,47.23 v1(14.53,47.23) ; U4.7 v2(61.25,11.52)
  L2_GND w0.203: v2(61.25,11.52) 61.25,11.64 61.13,11.75 v3(61.13,12.55)
  L3_SIG w0.095: v3(61.13,12.55) 61.13,14.85 60.4,15.58 59.92,15.58 59.72,15.78 59.72,16.09 60.63,17 60.63,19.29 60.37,19.54 60.37,23.6 60.12,23.85 60.12,24.15 60.04,24.24 60.04,33.6 58.47,35.16 58.47,42.4 60.25,44.18 60.25,46.59 60.5,46.84 v3(60.5,47.48)
  L6_SIG w0.095: v3(60.5,47.48) 60.5,48.5 59.7,49.3 59.7,49.4 57.81,51.29 27.67,51.29 27.59,51.2 27.25,51.2 27.17,51.29 19.61,51.29 15.42,47.1 14.66,47.1 v1(14.53,47.23)
PS_MIO00_500_JX4: length 48.2
  TOP w0.14: U1.E26 v1(43.22,17.59)
  L15_SIG w0.095: v1(84,12.17) 84,12.55 83.24,13.32 78.03,13.32 75.49,15.86 67.87,15.86 67.24,15.22 66.06,15.22 65.98,15.14 65.29,15.14 65.08,15.35 62.25,15.35 62.17,15.26 61.56,15.26 60.89,14.59 57.58,14.59 56.95,15.22 53.9,15.22 53.65,14.97 53.01,14.97 52.38,14.33 49.84,14.33 48.82,15.35 44.88,15.35 44.12,16.11 44.12,16.68 v1(43.22,17.59)
  BOTTOM w0.14: v1(84,12.17) JX4.97
PS_MIO01_500_QSPI0_SS_B: length 69.1
  TOP w0.14: v1(67.74,58.02) 67.62,57.89 U13.C2 ; U1.D26 v1(44.22,17.59)
  L4_SIG w0.095: v1(67.74,58.02) 69.01,58.02 71.05,55.99 v1(71.05,53.96)
  L7_SIG w0.095: v1(71.05,53.96) 71.05,49.87 70.96,49.78 70.96,48.97 70.66,48.68 70.66,45.57 71.93,44.3 71.93,43.46 71.73,43.25 71.73,42.97 71.93,42.76 71.93,39.16 68.95,36.18 66.22,36.18 65.36,35.32 65.36,33.2 64.55,32.39 64.27,32.39 64.1,32.22 64.1,31.97 63.72,31.59 63.47,31.59 63.3,31.42 63.3,31.17 62.92,30.79 62.67,30.79 62.5,30.62 62.5,30.34 61.6,29.45 60.38,29.45 59.87,28.94 59.87,27.68 59.52,27.32 59.52,24.84 58.89,24.2 58.89,23.57 58.25,22.94 51.65,22.94 51.27,22.56 49.11,22.56 48.7,22.15 44.63,22.15 44.41,21.93 44.07,21.93 43.88,21.73 43.88,21.45 43.36,20.93 43.07,20.93 42.88,20.73 42.88,20.4 42.63,20.15 42.63,18.38 43.08,17.93 43.36,17.93 43.7,17.59 v1(44.22,17.59)
  BOTTOM w0.14: v1(67.74,58.02) 67.74,58.27 R28.2
PS_MIO02_500_QSPI0_IO0: length 70.9
  TOP w0.14: v6(66.11,57.13) U13.D3 ; U1.E25 v1(43.22,18.59)
  L7_SIG w0.095: v6(66.11,57.13) 68.76,57.13 69.71,58.08 72,58.08 74.35,55.73 74.35,52.31 72.63,50.59 72.63,42.88 72.44,42.69 72.44,38.97 68.89,35.41 68.12,35.41 67.5,34.79 67.47,34.79 67.08,34.4 66.98,34.4 66.3,33.72 66.3,32.77 66.12,32.59 66.02,32.59 63.9,30.47 63.9,30.37 63.72,30.19 63.62,30.19 62.3,28.87 62.3,28.77 62.12,28.59 62.02,28.59 61.5,28.07 61.5,27.97 61.32,27.79 61.22,27.79 60.7,27.27 60.7,27.17 60.52,26.99 60.42,26.99 60,26.57 60,23.86 59.61,23.47 59.51,23.47 58.3,22.25 55.25,22.25 54.57,21.57 49.2,21.57 48.69,21.06 45.17,21.06 43.78,19.67 43.78,19.2 43.22,18.63 v1(43.22,18.59)
  BOTTOM w0.14: v6(66.11,57.13) 64.71,58.53 R120.1
PS_MIO03_500_QSPI0_IO1: length 67.7
  TOP w0.14: v1(71.3,49.64) 71.43,49.77 R119.1 71.43,53.58 71.81,53.96 v1(71.81,55.35) 71.3,55.86 71.05,55.86 69.78,57.13 67.11,57.13 U13.D2 ; U1.D25 v1(44.22,18.59)
  L7_SIG w0.095: v1(44.22,18.59) 43.78,18.15 43.17,18.15 42.85,18.47 42.85,19.74 45.04,21.93 47.36,21.93 47.46,21.83 48.69,21.83 49.2,22.33 51.36,22.33 51.74,22.71 58.35,22.71 59.11,23.48 59.11,24.11 59.74,24.75 59.74,27.03 60.1,27.39 60.1,27.42 60.47,27.79 60.52,27.79 60.7,27.97 60.7,28.02 61.07,28.39 61.13,28.39 61.5,28.77 61.5,28.82 62.87,30.19 62.92,30.19 63.1,30.37 63.1,30.42 63.47,30.79 63.53,30.79 63.9,31.17 63.9,31.19 64.31,31.6 64.57,31.6 65.58,32.62 65.58,35.03 66.35,35.8 68.89,35.8 72.19,39.1 72.19,42.75 72.41,42.97 72.41,43.25 72.19,43.47 72.19,45.32 71.17,46.34 71.17,48.87 71.43,49.13 71.43,49.51 v1(71.3,49.64)
PS_MIO04_500_QSPI0_IO2: length 74.3
  TOP w0.14: U13.C4 68.11,56.12 69.9,56.12 70.66,55.35 v1(70.66,53.19) ; U1.F24 v1(42.22,19.59)
  L7_SIG w0.095: v1(42.22,19.59) 42.22,20.11 41.88,20.45 41.88,20.73 42.17,21.03 42.86,21.03 42.98,21.15 43.26,21.15 43.65,21.54 43.65,21.82 43.98,22.15 44.3,22.15 45.07,22.93 47.36,22.93 47.84,22.45 48.69,22.45 49.02,22.78 51.18,22.78 51.56,23.16 58.16,23.16 58.66,23.66 58.66,24.3 59.3,24.93 59.3,27.6 59.62,27.92 59.62,29.06 60.38,29.83 60.96,29.83 61.7,30.56 61.7,30.62 62.07,30.99 62.18,30.99 62.5,31.31 62.5,31.42 62.67,31.59 62.78,31.59 63.3,32.11 63.3,32.22 63.67,32.59 63.72,32.59 64.1,32.96 64.1,33.02 64.27,33.19 64.33,33.19 64.7,33.57 64.7,33.82 64.7,33.82 64.7,35.29 66.85,37.45 66.85,39.35 67.24,39.73 67.87,39.73 68.25,39.35 68.25,36.94 68.44,36.75 68.82,36.75 71.3,39.22 71.3,44.3 70.28,45.32 70.28,48.88 70.66,49.26 v1(70.66,53.19) 70.66,56.62 v1(71.05,57)
  BOTTOM w0.14: R121.1 71.3,57.26 v1(71.05,57)
PS_MIO05_500_QSPI0_IO3: length 68.3
  TOP w0.14: U13.D4 66.58,55.62 66.09,56.12 65.33,56.12 64.95,56.5 64.95,56.88 v1(64.31,57.51) ; U1.C26 v1(45.22,17.59)
  L7_SIG w0.095: v1(45.22,17.59) 45.22,17.59 44.76,17.13 43.23,17.13 43.11,17.25 43.07,17.25 42.88,17.45 42.88,17.48 42.11,18.25 42.07,18.25 41.88,18.45 41.88,20.13 41.65,20.36 41.65,20.82 42.08,21.25 42.56,21.25 42.88,21.57 42.88,21.73 43.22,22.07 43.48,22.07 43.88,22.47 43.88,22.73 44.07,22.93 44.33,22.93 44.5,23.1 44.7,23.1 44.76,23.15 47.45,23.15 47.63,22.97 48.89,22.97 48.92,23 51.08,23 51.46,23.38 51.58,23.38 52.05,23.85 52.33,23.85 52.81,23.38 54.57,23.38 55.04,23.86 57.58,23.86 58.85,25.13 58.85,28.68 59.23,29.06 59.23,29.32 60.11,30.19 60.52,30.19 60.7,30.37 60.7,30.53 61.16,30.99 61.32,30.99 61.5,31.17 61.5,31.33 61.96,31.79 62.12,31.79 62.3,31.97 62.3,32.13 62.76,32.59 62.92,32.59 63.1,32.77 63.1,32.93 63.56,33.39 63.72,33.39 63.9,33.57 63.9,34.52 64.02,34.64 64.02,35.25 65.58,36.81 65.58,45.7 66.6,46.72 66.6,55.1 65.08,56.62 65.08,56.75 v1(64.31,57.51)
  BOTTOM w0.14: R122.1 v1(64.31,57.51)
PS_MIO06_500_QSPI0_SCLK: length 68.6
  TOP w0.14: v1(60.63,57.64) 60.63,56.37 62.41,54.59 62.41,48.88 61.52,47.99 v1(61.52,47.48) ; U13.B2 68.19,57.62 68.12,57.69 v6(68.08,57.69) ; U1.F23 v1(42.22,20.59)
  L3_SIG w0.095: v1(61.52,47.48) 61.52,47.61 61.27,47.86 55.42,47.86 54.92,47.35 53.01,47.35 52.5,47.86 49.46,47.86 48.82,47.23 48.82,43.42 47.55,42.15 47.17,42.15 46.79,41.76 46.79,22.33 46.53,22.08 45.01,22.08 44.61,21.68 44.61,19.5 44.36,19.25 44.07,19.25 43.25,20.07 42.7,20.07 42.22,20.56 v1(42.22,20.59)
  L17_SIG w0.095: v1(60.63,57.64) 61.14,58.15 65.37,58.15 65.84,57.68 67.88,57.68 67.89,57.69 v6(68.08,57.69)
  BOTTOM w0.14: R116.1 v1(60.63,57.64)
PS_MIO07_500_USB_RESET_B: length 46.4
  TOP w0.14: U1.E23 v1(43.22,20.59) ; U15.27 v1(22.16,49.4)
  L3_SIG w0.095: v1(43.22,20.59) 43.2,20.59 42.76,21.03 40.3,21.03 38.4,22.93 38.32,22.93 38,23.25 37.03,23.25 36.36,23.93 35.41,23.93 35.09,24.25 35.07,24.25 34.88,24.45 34.88,24.47 33.09,26.25 33.07,26.25 31.88,27.45 31.88,27.47 31.09,28.25 31.07,28.25 29.88,29.45 29.88,29.73 29.9,29.75 29.9,30.46 30.79,31.35 30.79,43.92 30.11,44.6 29.76,44.6 29.56,44.8 29.56,45.15 28.12,46.59 27.18,46.59 25.38,48.39 24.21,48.39 23.55,47.73 22.86,47.73 22.15,48.44 22.15,49.38 v1(22.16,49.4)
  BOTTOM w0.14: R31.2 42.99,20.36 v1(43.22,20.59)
PS_MIO08_500_ETH0_RESETN: length 50.9
  TOP w0.14: U1.A24 v1(47.22,19.59)
  L14_SIG w0.095: v3(18.98,4.05) 18.98,3.73 19.93,2.78 24.31,2.78 25.41,3.88 27.24,3.88 27.46,3.66 30.41,3.66 31.04,4.3 32.95,4.3 34.12,5.47 44.09,5.47 v3(45.14,4.43)
  L18_SIG w0.095: v3(45.14,4.43) 45.14,5.7 45.26,5.82 45.26,6.97 45.99,7.69 45.99,9.98 48.31,12.3 48.31,13.7 49.07,14.46 49.07,16.87 48.69,17.25 48.69,19.99 48.51,20.17 48.24,20.17 48.06,19.99 48.06,19.29 47.93,19.16 47.65,19.16 v1(47.22,19.59)
  L19_GND w0.203: v4(18.47,4.05) v3(18.98,4.05)
  BOTTOM w0.14: R32.2 47.01,19.79 v1(47.22,19.59) ; v4(18.47,4.05) 18.17,4.34 U10.16
PS_MIO09_500_USB_CLK_PD: length 57
  TOP w0.14: U1.D24 v1(44.22,19.59) ; v1(17.83,57.13) 16.98,57.98 Y3.1 16.98,59.46 R27.1
  L3_SIG w0.095: v1(44.22,19.59) 44.22,19.62 43.71,20.12 43.71,21.01 43.48,21.25 42.07,21.25 41.4,21.93 41.36,21.93 41.36,21.93 41.07,21.93 41.07,21.93 40.36,21.93 40.36,21.93 39.93,21.93 39.56,22.31 39.56,22.73 39.36,22.93 39.26,22.93 39.01,23.18 39.01,23.28 38.36,23.93 38.34,23.93 38.28,23.98 36.61,23.98 36.45,24.15 36.17,24.15 31.66,28.67 31.66,31.35 31.65,31.36 31.65,43.82 30.15,45.32 30.15,46.84 29.14,47.86 26.95,47.86 25.55,49.26 25.55,49.79 24.06,51.29 24.06,52.43 19.36,57.13 v1(17.83,57.13)
PS_MIO10_500_JX4: length 42.7
  TOP w0.14: U1.A25 v1(47.22,18.59)
  L15_SIG w0.095: v1(84.38,16.24) 84.13,16.49 82.22,16.49 81.46,15.73 80.82,15.73 80.32,15.22 79.17,15.22 78.54,15.86 78.54,15.98 77.9,16.62 77.27,16.62 76.89,17 73.71,17 72.82,17.89 65.33,17.89 64.95,18.27 61.27,18.27 60.76,17.76 58.09,17.76 57.84,17.51 54.41,17.51 52.76,19.16 48.57,19.16 48,18.59 v1(47.22,18.59)
  BOTTOM w0.14: JX4.87 84.45,16.17 v1(84.38,16.24)
PS_MIO11_500_JX4: length 41.1
  TOP w0.14: U1.B26 v1(46.22,17.59)
  L15_SIG w0.095: v1(46.22,17.59) 45.77,18.03 45.77,18.78 46.15,19.16 47.42,19.16 48.19,19.92 52.76,19.92 54.3,18.37 57.13,18.37 57.15,18.4 58.85,18.4 59.11,18.14 60.5,18.14 61.01,18.65 62.03,18.65 62.54,19.16 76.89,19.16 78.79,17.25 79.81,17.25 80.19,16.87 v1(80.19,16.24)
  BOTTOM w0.14: JX4.88 80.26,16.17 v1(80.19,16.24)
PS_MIO12_500_JX4: length 42.9
  L4_SIG w0.095: v1(79.55,16.31) 79.68,16.18 79.68,15.48 78.03,13.82 75.49,13.82 73.46,11.79 71.43,11.79 70.66,11.03 58.85,11.03 57.76,12.13 57.5,12.13 56.82,12.81 53.9,12.81 53.39,12.3 49.46,12.3 48.19,13.57 47.3,13.57 46.28,12.55 45.77,12.55 45.26,13.06 v1(45.26,13.44)
  BOTTOM w0.14: R60.2 45.32,13.49 v1(45.26,13.44) ; v1(79.55,16.31) 79.55,16.59 79.94,16.97 JX4.86
PS_MIO13_500_JX4: length 42.9
  TOP w0.14: U1.B25 v1(46.22,18.59)
  L15_SIG w0.095: v1(84.76,14.33) 84.51,14.59 78.03,14.59 76,16.62 71.87,16.62 71.85,16.6 66.5,16.6 66.22,16.87 63.04,16.87 62.54,16.36 57.58,16.36 57.2,16.75 54.66,16.75 53.03,18.37 48.57,18.37 48.33,18.14 46.66,18.14 v1(46.22,18.59)
  BOTTOM w0.14: JX4.91 85,14.57 v1(84.76,14.33)
PS_MIO14_500_JX4: length 48.7
  TOP w0.14: U1.D23 v1(44.22,20.59)
  L15_SIG w0.095: v1(44.22,20.59) 44.22,20.52 43.74,20.05 43.74,18.58 45.07,17.25 45.27,17.25 46.79,15.73 49.2,15.73 49.71,15.22 52.5,15.22 52.88,15.6 57.08,15.6 57.84,14.84 60.63,14.84 61.77,15.98 62.54,15.98 62.66,15.86 65.84,15.86 66.22,16.24 75.87,16.24 78.28,13.82 v1(85.14,13.82)
  BOTTOM w0.14: v1(85.14,13.82) 85.2,13.77 JX4.93
PS_MIO15_500_JX4: length 44.2
  TOP w0.14: U1.C24 v1(45.22,19.59)
  L15_SIG w0.095: v1(45.22,19.59) 45.8,20.17 47.68,20.17 48.19,20.68 52.88,20.68 54.41,19.16 59.1,19.16 59.21,19.05 59.51,19.05 59.62,19.16 62.03,19.16 62.41,19.54 79.3,19.54 79.94,18.9 82.48,18.9 82.84,18.54 82.91,18.61 83.19,18.61 83.39,18.41 83.39,18.13 83.32,18.06 v1(84.38,17)
  BOTTOM w0.14: JX4.85 84.41,16.97 v1(84.38,17)
PS_MIO16_501_ETH0_TX_CLK: length 51.3
  TOP w0.14: U1.G21 v1(41.22,22.59)
  L17_SIG w0.095: v1(30.02,7.86) 30.02,7.98 30.41,8.36 30.41,9.89 30.15,10.14 28.22,10.14 28.01,10.34 28.01,10.7 28.22,10.9 30.41,10.9 30.66,11.16 30.66,11.41 30.41,11.67 30.15,11.67 29.9,11.92 29.9,13.19 30.15,13.44 30.66,13.44 30.91,13.7 30.91,14.84 31.17,15.09 33.83,15.09 34.72,15.98 34.72,18.73 34.43,19.03 34.01,19.03 33.71,18.73 33.71,16.24 33.2,15.73 30.53,15.73 29.9,16.36 29.9,17 29.64,17.25 29.64,20.5 31.07,21.93 31.14,21.93 31.21,22 35.42,22 35.49,21.93 36.42,21.93 36.42,21.97 36.61,22.16 36.9,22.16 36.92,22.15 36.96,22.19 37.47,22.19 37.73,21.93 40.54,21.93 41.2,22.59 v1(41.22,22.59)
  BOTTOM w0.14: v1(30.02,7.86) 29.9,7.86 29.75,7.71 29.75,7.71 29.54,7.5 29.54,7.49 29.39,7.35 29.39,6.97 28.25,5.83 27.37,5.83 27.36,5.82 27.23,5.82 27,5.59 26.11,5.59 25.86,5.34 U10.53
PS_MIO17_501_ETH0_TX_D0: length 52.1
  TOP w0.14: U1.G17 v1(41.22,26.59)
  L18_SIG w0.095: v1(27.48,7.09) 27.97,7.09 28.02,7.14 28.8,7.14 30.28,8.62 35.49,8.62 35.8,8.3 35.8,7.16 36.12,6.84 39.3,6.84 39.68,7.22 39.68,11.16 39.3,11.54 39.3,12.55 37.26,14.59 37.26,15.98 v1(37.77,16.49)
  BOTTOM w0.14: U10.50 27.23,6.84 v1(27.48,7.09) ; v1(41.22,26.59) 41.22,26.16 40.69,25.64 40.69,18.52 40.31,18.14 31.97,18.14 31.68,17.84 31.68,17.42 31.97,17.13 37.14,17.13 v1(37.77,16.49)
PS_MIO18_501_ETH0_TX_D1: length 50.3
  TOP w0.14: U1.G20 v1(41.22,23.59)
  L17_SIG w0.095: v3(41.71,6.46) 41.33,6.46 41.2,6.59 39.68,6.59 39.17,7.09 38.91,7.09 38.28,6.46 37.26,6.46 37.01,6.71 37.01,7.22 37.26,7.47 38.66,7.47 38.79,7.6 38.79,8.11 38.41,8.49 38.3,8.49 38.19,8.6 38.19,8.91 38.41,9.13 38.41,9.76 38.03,10.14 37.77,10.14 37.64,10.01 37.64,9.76 37.96,9.45 37.96,9.31 37.84,9.19 37.7,9.19 37.26,9.63 37.26,10.01 37.14,10.14 36.88,10.14 36.76,10.01 36.76,9.25 36.88,9.13 37.26,9.13 37.51,8.88 37.51,8.48 37.26,8.24 37.26,7.98 37.01,7.73 36.63,7.73 36.37,7.47 36.37,6.84 36.12,6.59 35.74,6.59 35.49,6.84 35.49,7.09 35.23,7.35 34.85,7.35 34.6,7.09 34.6,6.84 34.34,6.59 29.14,6.59 28.88,6.33 27.87,6.33 v1(27.61,6.59)
  L18_SIG w0.095: v3(41.71,6.46) 41.71,6.74 41.79,6.83 41.79,7.9 41.07,8.62 40.69,8.62 40.31,9 40.31,11.16 40.95,11.79 40.95,12.81 40.57,13.19 40.57,16.24 41.58,17.25 41.58,18.47 41.61,18.51 41.61,21.3 41.62,21.31 41.62,23.18 v1(41.22,23.59)
  BOTTOM w0.14: U10.51 27.37,6.34 v1(27.61,6.59)
PS_MIO19_501_ETH0_TX_D2: length 50.5
  TOP w0.14: U1.G19 v1(41.22,24.59)
  L17_SIG w0.095: v1(29.9,7.35) 30.41,6.84 32.69,6.84 32.95,7.09 32.95,8.43 33.13,8.62 33.39,8.62 33.58,8.43 33.58,7.09 33.83,6.84 33.96,6.84 34.22,7.09 34.22,8.43 34.4,8.62 34.66,8.62 34.85,8.43 34.85,7.98 35.1,7.73 35.87,7.73 36.12,7.98 36.12,9 36.37,9.25 36.37,10.27 36.63,10.52 38.79,10.52 39.68,9.63 39.68,7.47 40.31,6.84 40.82,6.84 41.07,7.09 41.07,7.89 41.3,8.11 41.61,8.11 41.84,7.89 41.84,7.35 v3(41.45,6.97)
  L18_SIG w0.095: v1(41.22,24.59) 40.69,24.07 40.69,17 40.31,16.62 40.31,13.85 39.55,13.09 39.55,11.92 40.06,11.41 40.06,8.87 40.57,8.36 40.95,8.36 41.45,7.86 v3(41.45,6.97)
  BOTTOM w0.14: v1(29.9,7.35) 29.75,7.2 29.75,6.57 29.28,6.1 29.28,5.96 28.9,5.58 28.38,5.58 28.36,5.56 28,5.56 28,5.56 27.48,5.56 27.47,5.56 27.34,5.56 27.11,5.32 26.35,5.32 25.87,4.84 U10.54
PS_MIO20_501_ETH0_TX_D3: length 52
  TOP w0.14: U1.H19 v1(40.22,24.59)
  L17_SIG w0.095: v3(38.28,14.84) 37.9,14.46 32.18,14.46 31.29,13.57 v3(31.29,11.67) 37.26,11.67 37.52,11.41 37.52,11.16 37.26,10.9 34.6,10.9 34.34,10.65 34.34,10.14 34.6,9.89 35.63,9.89 35.87,9.65 35.87,9.41 35.61,9.15 34.42,9.15 33.45,10.12 33.45,10.65 33.2,10.9 31.55,10.9 31.29,10.65 31.29,9.25 32.44,8.11 32.44,7.73 32.06,7.35 v1(30.41,7.35)
  L18_SIG w0.095: v3(38.28,14.84) 39.8,16.36 39.8,23.86 40.22,24.27 v1(40.22,24.59)
  BOTTOM w0.14: U10.55 25.88,4.34 26.59,5.06 27.22,5.06 27.46,5.29 27.58,5.29 27.59,5.3 27.89,5.3 27.89,5.29 28.47,5.29 28.49,5.32 29.26,5.32 29.62,4.95 29.92,4.95 30.13,5.17 30.13,5.57 30.26,5.7 30.26,7.2 v1(30.41,7.35)
PS_MIO21_501_ETH0_TX_CTL: length 50.6
  TOP w0.14: U1.F22 v1(42.22,21.59)
  L17_SIG w0.095: v1(26.72,4.43) 26.72,4.55 27.61,5.44 28.12,5.44 29.52,4.05 30.15,4.05 32.18,6.08 42.47,6.08 42.72,6.33 42.72,7.73 42.98,7.98 46.95,7.98 47.17,7.76 47.17,7.44 46.95,7.22 45.35,7.22 45.01,6.88 45.01,6.33 44.76,6.08 44.5,6.08 44.25,6.33 44.25,6.97 43.99,7.22 43.36,7.22 43.23,7.09 43.23,6.71 v3(43.61,6.33)
  L18_SIG w0.095: v3(43.61,6.33) 43.61,7.73 43.36,7.98 42.09,7.98 41.19,8.88 41.19,13.14 41.05,13.28 41.05,14.56 41.84,15.35 41.84,21.21 v1(42.22,21.59)
  BOTTOM w0.14: U10.56 26.14,3.84 v1(26.72,4.43)
PS_MIO22_501_ETH0_RX_CLK: length 52.4
  TOP w0.14: U1.G22 v1(41.22,21.59)
  L4_SIG w0.095: v1(41.22,21.59) 40.84,21.59 40.18,20.94 39.04,20.94 38.55,20.45 38.55,20.45 38.15,20.05 38.04,20.05 v3(37.71,19.72)
  L18_SIG w0.095: v1(27.1,9.76) 27.74,9.76 28.37,10.4 34.44,10.4 36.1,8.73 36.1,7.24 36.25,7.09 38.41,7.09 38.66,7.35 38.66,9.25 36.12,11.79 36.12,15.73 36.54,16.15 36.54,16.5 36.76,16.72 36.76,17 36.51,17.25 36.07,17.25 36.07,17.25 35.36,17.25 35.36,17.25 35.07,17.25 35.07,17.25 34.09,17.25 33.83,17.51 33.83,18.02 34.09,18.27 35.05,18.27 35.07,18.25 35.36,18.25 35.38,18.27 36.05,18.27 36.07,18.25 36.36,18.25 36.38,18.27 36.5,18.27 36.76,18.52 36.76,19.79 37.01,20.05 37.52,20.05 37.77,20.3 37.77,22.08 37.9,22.21 38.53,22.21 38.75,21.99 38.75,17.47 38.33,17.05 38.03,17.05 37.77,17.31 37.77,19.65 v3(37.71,19.72)
  BOTTOM w0.14: U10.46 26.19,8.84 v1(27.1,9.76)
PS_MIO23_501_ETH0_RX_D0: length 50.1
  TOP w0.14: U1.F20 v1(42.22,23.59)
  L17_SIG w0.095: v1(27.1,11.54) 27.74,12.17 29.39,12.17 29.41,12.19 29.41,12.19 29.64,12.42 29.64,12.94 29.26,13.32 27.74,13.32 27.36,13.7 27.36,15.09 27.1,15.35 27.1,15.6 27.61,16.11 27.61,18.78 27.36,19.03 26.85,19.03 26.6,19.29 26.6,19.79 26.85,20.05 27.36,20.05 27.61,20.3 27.61,20.78 27.74,20.9 28.05,20.9 28.07,20.93 28.36,20.93 28.56,20.73 28.56,17.45 28.5,17.39 28.5,16.36 29.01,15.86 29.01,15.48 28.75,15.22 28.12,15.22 27.87,14.97 27.87,14.33 28.12,14.08 29.39,14.08 29.64,14.33 29.64,15.73 28.88,16.5 28.88,20.8 29,20.93 29.35,20.93 29.78,21.36 29.78,21.63 30.07,21.93 30.35,21.93 30.67,22.25 31.36,22.25 32.04,22.93 41.54,22.93 42.2,23.59 v1(42.22,23.59)
  BOTTOM w0.14: U10.44 26.04,9.84 26.98,10.78 26.98,11.41 v1(27.1,11.54)
PS_MIO24_501_ETH0_RX_D1: length 50.1
  TOP w0.14: U1.J19 v1(39.22,24.59)
  BOTTOM w0.14: v1(39.22,24.59) 38.66,24.03 38.66,19.29 38.41,19.03 20.75,19.03 20.5,18.78 20.5,17.38 20.75,17.13 26.47,17.13 26.72,17.38 26.72,17.76 26.98,18.02 30.41,18.02 30.79,17.63 30.79,17.38 30.53,17.13 27.48,17.13 27.1,16.75 27.1,12.55 27.61,12.05 v1(27.61,11.54) 27.48,11.41 27.48,10.78 26.05,9.34 U10.45
PS_MIO25_501_ETH0_RX_D2: length 51.4
  TOP w0.14: U1.F19 v1(42.22,24.59)
  L7_SIG w0.095: v3(36.76,21.83) 36.88,21.7 36.88,21.45 37.26,21.06 38.28,21.06 38.88,21.66 38.88,21.73 39.07,21.93 39.14,21.93 39.68,22.46 39.68,22.59 40.34,23.25 40.36,23.25 41.7,24.59 v1(42.22,24.59)
  L18_SIG w0.095: v1(24.69,8.74) 24.94,9 24.94,10.01 25.69,10.76 34.43,10.76 36.39,8.8 36.39,7.94 36.59,7.74 37.02,7.74 37.26,7.98 37.26,8.26 37.48,8.48 37.48,8.76 37.39,8.84 37.39,9.63 35.61,11.41 35.61,16.62 35.36,16.87 30.79,16.87 30.66,17 30.66,18.02 30.89,18.25 32.56,18.25 32.82,18.5 32.82,19.67 32.88,19.72 32.88,19.73 33.07,19.93 33.08,19.93 33.33,20.17 34.22,20.17 34.47,19.92 34.47,19.29 34.72,19.03 35.36,19.03 35.61,19.29 35.61,20.47 36.07,20.93 36.37,20.93 36.76,21.32 v3(36.76,21.83)
  BOTTOM w0.14: U10.47 25.09,8.34 v1(24.69,8.74)
PS_MIO26_501_ETH0_RX_D3: length 50.3
  TOP w0.14: U1.H17 v1(40.22,26.59)
  L15_SIG w0.095: v3(26.21,15.98) 26.72,15.98 27.61,16.87 34.85,16.87 v3(35.23,16.49) 35.87,17.13 35.87,18.52 35.14,19.25 35.07,19.25 34.6,19.73 34.6,23.6 34.98,23.98 37.39,23.98 37.88,24.47 37.88,24.73 39.74,26.59 v1(40.22,26.59)
  L17_SIG w0.095: v1(24.66,8.21) 25.05,8.21 25.45,8.62 25.45,10.52 25.07,10.9 18.34,10.9 18.04,11.2 18.04,12.06 17.58,12.53 17.58,12.81 17.83,13.06 20.25,13.06 20.5,12.81 21.9,12.81 22.28,13.19 23.17,13.19 23.55,12.81 24.31,12.81 24.63,13.13 25.39,13.13 25.71,13.44 25.71,13.95 26.21,14.46 v3(26.21,15.98)
  BOTTOM w0.14: v1(24.66,8.21) 24.66,8.13 24.96,7.84 U10.48
PS_MIO27_501_ETH0_RX_CTL: length 51.4
  TOP w0.14: U1.F18 v1(42.22,25.59)
  L6_SIG w0.095: v3(34.22,24.59) 34.22,24.62 34.72,25.13 41.75,25.13 v1(42.22,25.59)
  L17_SIG w0.095: v3(34.22,24.59) 34.22,24.24 33.56,23.58 33.56,23.45 33.36,23.25 33.07,23.25 32.88,23.45 32.56,23.45 32.36,23.25 32.07,23.25 31.88,23.45 31.56,23.45 31.36,23.25 31.17,23.25 30.56,22.64 30.56,22.45 30.36,22.25 30.07,22.25 29.56,21.73 29.56,21.45 29.36,21.25 26.91,21.25 26.72,21.06 26.72,20.43 26.47,20.17 24.99,20.17 24.69,19.88 24.69,19.46 24.99,19.16 25.45,19.16 25.71,18.9 25.71,18.4 25.45,18.14 22.99,18.14 22.66,17.81 22.66,14.46 22.91,14.21 23.67,14.21 23.93,14.46 23.93,16.75 24.18,17 26.47,17 26.72,16.75 26.72,15.86 26.6,15.73 26.6,12.3 26.21,11.92 26.21,10.4 25.83,10.01 25.83,8.71 26.06,8.49 26.37,8.49 26.6,8.71 v1(26.6,11.54)
  BOTTOM w0.14: v1(26.6,11.54) 26.6,11.03 25.91,10.34 U10.43
PS_MIO28_501_USB0_D4: length 45.9
  TOP w0.14: U1.J18 v1(39.22,25.59) ; U15.7 26.07,54.19 v1(26.85,54.97)
  L3_SIG w0.095: v1(26.85,54.97) 26.87,54.95 26.87,54.69 26.95,54.62 27.64,54.62 27.79,54.47 27.79,54.33 27.61,54.16 26.65,54.16 26.42,53.93 26.42,52.64 26.72,52.33 26.72,50.91 26.98,50.65 27.99,50.65 28.26,50.39 28.26,49.27 28.53,49 29.9,49 31.42,47.48 31.42,45.83 32.38,44.87 32.38,44.71 32.82,44.27 32.82,32.49 33.58,31.73 33.58,31.48 33.9,31.16 34.15,31.16 36.63,28.68 36.63,27.54 37.24,26.93 37.36,26.93 37.56,26.73 37.56,26.61 38.08,26.09 38.33,26.09 38.56,25.86 38.56,25.13 38.76,24.93 40.51,24.93 40.77,25.2 40.77,25.81 40.62,25.97 39.59,25.97 v1(39.22,25.59)
PS_MIO29_501_USB0_DIR: length 46.8
  TOP w0.14: U1.E20 v1(43.22,23.59) ; U15.31 24.16,49.53 v1(24.31,49.38)
  L15_SIG w0.095: v3(41.2,30.59) 41.88,29.91 41.88,29.45 42.72,28.6 42.72,24.11 43.22,23.62 v1(43.22,23.59)
  L17_SIG w0.095: v3(41.2,30.59) 41.07,30.72 40.06,30.72 39.68,31.1 39.68,32.87 39.42,33.13 34.85,33.13 34.47,33.51 34.47,37.19 33.58,38.08 33.07,38.08 32.55,38.6 32.55,38.73 32.36,38.93 32.23,38.93 31.8,39.35 31.8,43.8 31.29,44.3 22.91,44.3 22.02,45.19 22.02,48.62 22.4,49 23.93,49 v1(24.31,49.38)
PS_MIO30_501_USB0_STP: length 50.2
  TOP w0.14: U1.K19 v1(38.22,24.59) ; U15.29 v1(23.16,49.39)
  L3_SIG w0.095: v1(33.22,29.59) 33.83,28.97 33.83,28.56 34.88,27.51 34.88,27.45 37.74,24.59 v1(38.22,24.59)
  L15_SIG w0.095: v1(33.22,29.59) 33.01,29.38 33.01,29.32 32.63,28.94 30.89,28.94 30.8,28.85 30.52,28.85 30.43,28.94 29.94,28.94 29.55,29.32 29.55,29.73 27.36,31.93 27.29,31.93 26.72,32.49 26.72,43.92 27.61,44.81 27.61,49.89 27.23,50.27 25.96,50.27 25.58,49.89 25.58,45.96 25.96,45.57 25.96,44.69 25.58,44.3 24.94,44.3 23.55,45.7 23.55,49 v1(23.16,49.39)
PS_MIO31_501_USB0_NXT: length 45.9
  TOP w0.14: U15.2 v1(25.94,51.69) ; U1.E21 v1(43.22,22.59)
  L3_SIG w0.095: v1(43.22,22.59) 43.22,22.74 42.8,23.15 42.8,23.75 42.47,24.09 41.99,24.09 41.66,23.75 41.66,22.36 41.48,22.18 40.97,22.18 40.69,22.46 40.69,23.81 40.53,23.97 39.04,23.97 39.02,23.98 38.61,23.98 38.39,24.21 37.04,24.21 36.55,24.69 36.55,24.73 32.77,28.51 32.77,29.87 31.93,30.72 31.93,31.39 31.88,31.45 31.88,44 31.08,44.8 31.08,44.9 30.66,45.32 30.66,46.97 29.39,48.24 27.61,48.24 25.07,50.78 25.07,51.42 25.35,51.69 v1(25.94,51.69)
PS_MIO32_501_USB0_D0: length 46.8
  TOP w0.14: U15.3 26.35,52.19 v1(26.85,52.69) ; U1.K17 v1(38.22,26.59)
  L3_SIG w0.095: v1(26.85,52.69) 26.85,52.52 26.94,52.43 26.94,51.29 27.07,51.16 28.27,51.16 28.4,51.29 28.4,51.34 28.53,51.47 28.7,51.47 28.86,51.31 28.86,49.44 28.98,49.31 29.24,49.31 29.41,49.49 29.41,51.54 29.54,51.67 31.42,51.67 31.55,51.54 31.55,51.16 31.42,51.04 30.25,51.04 30.13,50.91 30.13,49.38 31.8,47.71 31.8,45.96 32.61,45.15 32.61,44.8 32.8,44.6 33.16,44.6 33.71,44.05 33.71,38.87 33.65,38.82 33.65,32.63 34.6,31.69 34.6,31.41 34.78,31.22 35.06,31.22 37.62,28.67 37.66,28.67 39.36,26.96 39.47,26.96 39.63,26.8 39.63,26.41 39.41,26.19 39.1,26.19 38.88,26.41 38.88,26.92 38.61,27.18 38.08,27.18 37.95,27.06 37.95,26.85 v1(38.22,26.59)
PS_MIO33_501_USB0_D1: length 46.4
  TOP w0.14: U1.E22 v1(43.22,21.59) ; U15.4 v1(25.96,52.69)
  L3_SIG w0.095: v1(43.22,21.59) 43.25,21.59 43.74,22.08 43.74,24.59 43.18,25.15 42.93,25.15 42.6,25.48 42.6,25.84 42.34,26.09 42.06,26.09 41.76,25.79 41.76,24.39 41.56,24.19 39.14,24.19 35.88,27.45 35.88,28.17 35.56,28.49 35.56,28.73 32.56,31.73 32.56,44.18 31.76,44.98 31.76,45.08 31.56,45.28 31.46,45.28 31.04,45.7 31.04,47.23 29.64,48.62 28.25,48.62 26.47,50.4 26.47,51.92 25.96,52.44 v1(25.96,52.69)
PS_MIO34_501_USB0_D2: length 45.7
  TOP w0.14: U1.J16 v1(39.22,27.59) ; U15.5 26.34,53.19 v1(26.85,53.7)
  L3_SIG w0.095: v1(26.85,53.7) 26.85,53.45 27.36,52.94 27.36,52.31 27.87,51.8 29.16,51.8 29.92,52.56 31.04,52.56 32.06,51.54 32.06,51.04 31.17,50.15 30.66,50.15 30.41,49.89 30.41,49.64 32.82,47.23 32.82,45.83 34.22,44.43 34.22,39.07 33.88,38.73 33.88,38.45 34.22,38.11 34.22,33.07 35.56,31.73 35.56,31.53 35.99,31.1 35.99,30.81 36.88,29.93 37.36,29.93 37.56,29.73 37.56,29.45 38.07,28.93 38.36,28.93 38.56,28.73 38.56,28.25 38.86,27.94 40.03,27.94 40.04,27.93 40.39,27.93 41.78,26.55 41.78,26.41 41.51,26.14 40.9,26.14 40.68,26.36 40.68,26.97 40.46,27.18 39.62,27.18 v1(39.22,27.59)
PS_MIO35_501_USB0_D3: length 45.9
  TOP w0.14: U1.D19 v1(44.22,24.59) ; U15.6 v1(25.95,53.69)
  L3_SIG w0.095: v1(25.95,53.69) 25.34,53.69 24.94,54.08 24.94,54.93 25.34,55.33 27.26,55.33 27.48,55.1 28.88,55.1 32.44,51.54 32.44,50.91 31.55,50.02 31.55,49 33.27,47.28 33.27,46.1 34.26,45.12 34.26,44.8 34.55,44.5 34.55,38.45 34.47,38.36 34.47,33.82 40.13,28.15 41.13,28.15 42.56,26.73 42.56,26.45 43.07,25.93 43.36,25.93 43.56,25.73 43.56,25.25 v1(44.22,24.59)
PS_MIO36_501_USB0_CLK: length 51.7
  TOP w0.14: v1(25.96,50.78) 25.55,51.19 U15.1 ; U1.K16 v1(38.22,27.59)
  L18_SIG w0.095: v1(25.96,50.78) 25.45,51.29 25.45,53.7 24.18,54.97 23.29,54.97 22.53,55.73 22.53,56.37 22.91,56.75 25.2,56.75 25.6,56.35 26.24,56.35 27.23,55.35 27.23,52.56 29.39,50.4 29.39,47.23 30.79,45.83 30.79,44.69 31.42,44.05 31.93,44.05 32.05,43.93 32.36,43.93 32.82,43.47 32.82,40.49 32.25,39.93 32.07,39.93 31.88,39.73 31.88,39.55 31.29,38.97 31.04,38.97 30.79,38.72 30.79,34.27 31.04,34.02 32.69,34.02 32.88,33.83 32.88,33.45 33.07,33.25 33.21,33.25 34.34,32.11 34.34,30.97 34.85,30.46 37.39,30.46 37.64,30.21 37.64,28.16 v1(38.22,27.59)
PS_MIO37_501_USB0_D5: length 45.9
  TOP w0.14: U15.9 24.66,55.83 v1(24.94,56.12) ; U1.D20 v1(44.22,23.59)
  L3_SIG w0.095: v1(44.22,23.59) 44.63,24 44.63,25.51 44.56,25.58 44.56,25.73 41.36,28.93 40.45,28.93 40.13,29.25 40.07,29.25 35.4,33.93 34.88,34.45 34.88,42.73 35.07,42.93 35.07,43.25 34.88,43.45 34.88,44.74 34.94,44.8 34.94,45.43 34.37,46 33.69,46 33.49,46.2 33.49,47.69 32.31,48.88 32.31,50.27 32.69,50.65 32.69,51.7 28.96,55.43 28.42,55.43 28.39,55.39 28.11,55.39 28.07,55.43 27.78,55.43 27.6,55.61 25.96,55.61 25.45,56.12 v1(24.94,56.12)
PS_MIO38_501_USB0_D6: length 47.5
  TOP w0.14: U1.D21 v1(44.22,22.59) ; v1(24.31,56.12) 24.16,55.97 U15.10
  L3_SIG w0.095: v1(24.31,56.12) 24.69,56.5 25.9,56.5 26.05,56.35 26.38,56.35 26.53,56.5 28.4,56.5 33.2,51.7 33.2,49.38 34.22,48.37 34.22,46.72 34.8,46.14 34.8,46.1 35.13,45.77 35.16,45.77 35.61,45.32 35.61,34.71 39.07,31.25 39.27,31.25 40.59,29.93 41.36,29.93 44.56,26.73 44.56,26.47 44.88,26.14 44.88,25.74 44.88,25.73 44.88,23.25 v1(44.22,22.59)
PS_MIO39_501_USB0_D7: length 50.8
  TOP w0.14: U1.C21 v1(45.22,22.59) ; U15.13 22.66,55.87 v1(22.91,56.12)
  L3_SIG w0.095: v1(45.22,22.59) 45.56,22.93 45.56,26.73 41.95,30.33 41.43,30.33 41.34,30.25 41.06,30.25 40.97,30.33 40.95,30.33 39.56,31.73 39.56,31.73 35.87,35.42 35.87,45.57 35.44,46 35.22,46 35.02,46.2 35.02,46.42 34.6,46.84 34.6,48.62 33.58,49.64 33.58,52.41 28.22,57.77 24.56,57.77 v1(22.91,56.12)
PS_MIO40_501_SD0_CLK: length 69.6
  TOP w0.14: U11.9 v2(8.05,17.38) ; U1.C22 v1(45.22,21.59)
  L2_GND w0.203: v2(8.05,17.38) v3(8.43,17.76)
  L18_SIG w0.095: v1(45.22,21.59) 45.74,21.59 46.07,21.93 47.36,21.93 47.55,21.73 47.55,21.45 47.36,21.25 47.07,21.25 46.55,20.73 46.55,20.45 46.36,20.25 45.36,20.25 44.76,19.65 44.76,17.25 45.01,17 45.01,15.86 43.87,14.71 43.87,13.32 44.38,12.81 44.38,9.38 44.25,9.25 44.25,6.2 43.66,5.62 36.12,5.62 34.93,4.43 32.31,4.43 30.28,6.46 29.52,6.46 28.75,5.7 27.48,5.7 27.1,5.32 26.72,5.32 23.81,8.23 23.03,8.23 21.9,9.36 21.9,10.27 20.75,11.41 15.67,11.41 15.42,11.16 9.96,11.16 8.43,12.68 v3(8.43,17.76)
